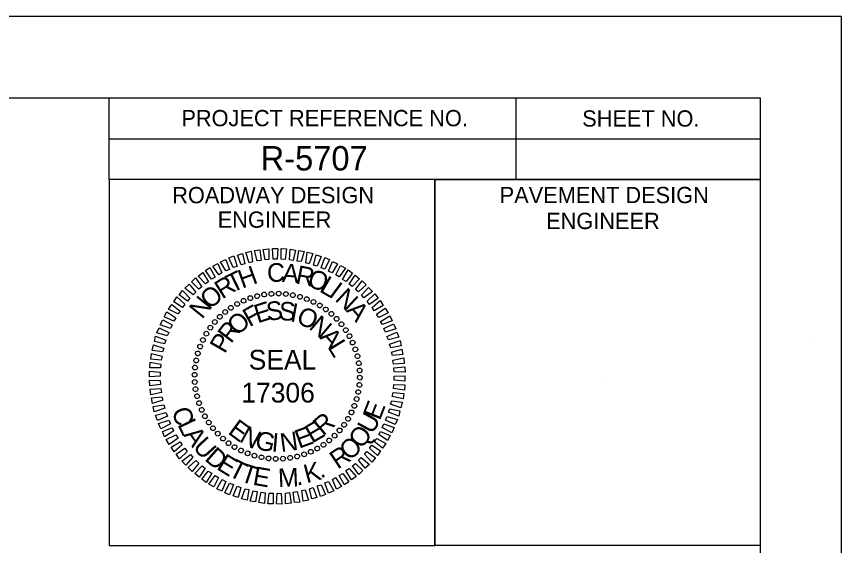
# Model space of a CAD drawing. Extents: x 573078 to 573116.6, y -55221.3 to -55199.3.
# Drawn here: x 573106.94 to 573112.01, y -55202.55 to -55199.3 of the extents above; entities that cross this region are included whole.
import ezdxf

# ---------------------------------------------------------------- set-up
doc = ezdxf.new("R2010")
doc.units = 0
for name, color, linetype in [('Prop Dimension', 7, 'Continuous'), ('Scratch_Level_1', 7, 'Continuous'), ('Sheet Clip Boundary CELL', 7, 'Continuous'), ('Sheet Data Field CELL', 7, 'Continuous'), ('Sheet Plan CELL', 7, 'Continuous'), ('Sheet Plot Border Inside CELL', 7, 'Continuous')]:
    doc.layers.add(name, color=color, linetype=linetype)

msp = doc.modelspace()

# ---------------------------------------------------------------- linework, layer by layer
at = {"layer": 'Prop Dimension'}
for p, q in [((573108.38, -55201.0284), (573108.38, -55201.0284)), ((573108.4225, -55201.0163), (573108.4225, -55201.0163)), ((573108.467, -55201.0082), (573108.467, -55201.0082)), ((573108.5105, -55201.0021), (573108.5105, -55201.0021)), ((573108.555, -55201.0012), (573108.555, -55201.0012)), ((573108.5996, -55201.0041), (573108.5996, -55201.0041)), ((573108.6432, -55201.0113), (573108.6432, -55201.0113)), ((573108.6857, -55201.0203), (573108.6857, -55201.0203)), ((573108.2999, -55201.0649), (573108.2999, -55201.0649)), ((573108.3395, -55201.0446), (573108.3395, -55201.0446)), ((573108.7283, -55201.0345), (573108.7283, -55201.0345)), ((573108.7688, -55201.0527), (573108.7688, -55201.0527)), ((573108.8081, -55201.073), (573108.8081, -55201.073)), ((573108.2261, -55201.1135), (573108.2261, -55201.1135)), ((573108.2614, -55201.0883), (573108.2614, -55201.0883)), ((573108.8446, -55201.0984), (573108.8446, -55201.0984)), ((573108.8801, -55201.1256), (573108.8801, -55201.1256)), ((573108.1622, -55201.1753), (573108.1622, -55201.1753)), ((573108.1925, -55201.1438), (573108.1925, -55201.1438)), ((573108.9114, -55201.156), (573108.9114, -55201.156)), ((573108.1349, -55201.2107), (573108.1349, -55201.2107)), ((573108.9418, -55201.1895), (573108.9418, -55201.1895)), ((573108.9672, -55201.2248), (573108.9672, -55201.2248)), ((573108.0893, -55201.2867), (573108.0893, -55201.2867)), ((573108.1095, -55201.2471), (573108.1095, -55201.2471)), ((573108.9904, -55201.2633), (573108.9904, -55201.2633)), ((573108.071, -55201.3272), (573108.071, -55201.3272)), ((573109.0106, -55201.3029), (573109.0106, -55201.3029)), ((573108.0569, -55201.3697), (573108.0569, -55201.3697)), ((573109.0268, -55201.3434), (573109.0268, -55201.3434)), ((573109.039, -55201.3859), (573109.039, -55201.3859)), ((573108.0479, -55201.4123), (573108.0479, -55201.4123)), ((573109.0471, -55201.4305), (573109.0471, -55201.4305)), ((573108.0407, -55201.4557), (573108.0407, -55201.4557)), ((573109.0532, -55201.4739), (573109.0532, -55201.4739)), ((573108.0377, -55201.5002), (573108.0377, -55201.5002)), ((573108.546, -55201.5095), (573108.546, -55201.5095)), ((573109.0543, -55201.5185), (573109.0543, -55201.5185)), ((573108.0386, -55201.5448), (573108.0386, -55201.5448)), ((573108.0447, -55201.5884), (573108.0447, -55201.5884)), ((573109.0511, -55201.563), (573109.0511, -55201.563)), ((573108.0528, -55201.633), (573108.0528, -55201.633)), ((573109.0442, -55201.6067), (573109.0442, -55201.6067)), ((573108.065, -55201.6755), (573108.065, -55201.6755)), ((573109.0208, -55201.6917), (573109.0208, -55201.6917)), ((573109.0349, -55201.6492), (573109.0349, -55201.6492)), ((573108.0812, -55201.716), (573108.0812, -55201.716)), ((573109.0025, -55201.7322), (573109.0025, -55201.7322)), ((573108.1014, -55201.7554), (573108.1014, -55201.7554)), ((573108.1248, -55201.7939), (573108.1248, -55201.7939)), ((573108.9823, -55201.7716), (573108.9823, -55201.7716)), ((573108.15, -55201.8294), (573108.15, -55201.8294)), ((573108.9296, -55201.8436), (573108.9296, -55201.8436)), ((573108.9571, -55201.808), (573108.9571, -55201.808)), ((573108.1804, -55201.8627), (573108.1804, -55201.8627)), ((573108.2119, -55201.8931), (573108.2119, -55201.8931)), ((573108.8993, -55201.8749), (573108.8993, -55201.8749)), ((573108.2472, -55201.9205), (573108.2472, -55201.9205)), ((573108.2837, -55201.9457), (573108.2837, -55201.9457)), ((573108.8304, -55201.9307), (573108.8304, -55201.9307)), ((573108.866, -55201.9052), (573108.866, -55201.9052)), ((573108.3233, -55201.966), (573108.3233, -55201.966)), ((573108.3638, -55201.9842), (573108.3638, -55201.9842)), ((573108.7121, -55201.9903), (573108.7121, -55201.9903)), ((573108.7526, -55201.9741), (573108.7526, -55201.9741)), ((573108.7919, -55201.9538), (573108.7919, -55201.9538)), ((573108.4063, -55201.9984), (573108.4063, -55201.9984)), ((573108.4488, -55202.0076), (573108.4488, -55202.0076)), ((573108.4922, -55202.0146), (573108.4922, -55202.0146)), ((573108.5368, -55202.0177), (573108.5368, -55202.0177)), ((573108.5813, -55202.0166), (573108.5813, -55202.0166)), ((573108.625, -55202.0105), (573108.625, -55202.0105)), ((573108.6695, -55202.0024), (573108.6695, -55202.0024))]:
    msp.add_line(p, q, dxfattribs=at)
for points in [[(573108.4711, -55200.7946), (573108.4598, -55200.7298), (573108.4943, -55200.7258), (573108.4954, -55200.7915)], [(573108.5217, -55200.7895), (573108.5165, -55200.7238), (573108.5501, -55200.7247), (573108.546, -55200.7906)], [(573108.5703, -55200.7906), (573108.5703, -55200.7247), (573108.6036, -55200.7258), (573108.5946, -55200.7915)], [(573108.6209, -55200.7935), (573108.625, -55200.7278), (573108.6583, -55200.7339), (573108.6452, -55200.7976)], [(573108.2756, -55200.8412), (573108.2492, -55200.7825), (573108.2796, -55200.7703), (573108.301, -55200.8351)], [(573108.3253, -55200.825), (573108.3019, -55200.7643), (573108.3334, -55200.755), (573108.3464, -55200.8178)], [(573108.3739, -55200.8117), (573108.3525, -55200.7481), (573108.3869, -55200.7409), (573108.395, -55200.8068)], [(573108.4225, -55200.8007), (573108.4063, -55200.7359), (573108.4396, -55200.7328), (573108.4468, -55200.7976)], [(573108.6695, -55200.8016), (573108.6785, -55200.7368), (573108.7121, -55200.742), (573108.6938, -55200.8048)], [(573108.7211, -55200.8129), (573108.7312, -55200.7469), (573108.7656, -55200.755), (573108.7424, -55200.8178)], [(573108.7697, -55200.8259), (573108.785, -55200.7631), (573108.8162, -55200.7733), (573108.791, -55200.8331)], [(573108.1876, -55200.8867), (573108.15, -55200.832), (573108.1815, -55200.8158), (573108.2067, -55200.8745)], [(573108.231, -55200.8624), (573108.1986, -55200.8057), (573108.2301, -55200.7915), (573108.2533, -55200.8534)], [(573108.8153, -55200.8441), (573108.8385, -55200.7805), (573108.8669, -55200.7926), (573108.8385, -55200.8513)], [(573108.8608, -55200.8635), (573108.8862, -55200.8036), (573108.9175, -55200.8178), (573108.8831, -55200.8745)], [(573108.9074, -55200.8867), (573108.9348, -55200.8291), (573108.9652, -55200.8462), (573108.9267, -55200.8988)], [(573108.1046, -55200.9425), (573108.0609, -55200.8939), (573108.0884, -55200.8725), (573108.1237, -55200.9292)], [(573108.143, -55200.9121), (573108.1055, -55200.8603), (573108.1318, -55200.8412), (573108.1653, -55200.8999)], [(573108.947, -55200.9141), (573108.9823, -55200.8554), (573109.0086, -55200.8765), (573108.9692, -55200.9263)], [(573108.0641, -55200.9737), (573108.0195, -55200.9292), (573108.0438, -55200.9049), (573108.0832, -55200.9596)], [(573108.9884, -55200.9445), (573109.0259, -55200.8887), (573109.0523, -55200.911), (573109.0077, -55200.9587)], [(573109.0268, -55200.9758), (573109.0685, -55200.9231), (573109.0928, -55200.9474), (573109.0462, -55200.9911)], [(573107.9952, -55201.0478), (573107.9426, -55201.0082), (573107.9648, -55200.9818), (573108.0094, -55201.0295)], [(573108.0305, -55201.0093), (573107.979, -55200.9677), (573108.0042, -55200.9445), (573108.0467, -55200.9931)], [(573109.0633, -55201.0113), (573109.1069, -55200.9636), (573109.1312, -55200.9879), (573109.0786, -55201.0275)], [(573107.9648, -55201.0862), (573107.9102, -55201.0518), (573107.9293, -55201.0223), (573107.9779, -55201.0669)], [(573109.0988, -55201.0478), (573109.1454, -55201.0021), (573109.1666, -55201.0295), (573109.113, -55201.068)], [(573107.9345, -55201.1267), (573107.8778, -55201.0964), (573107.898, -55201.068), (573107.9507, -55201.1085)], [(573109.1292, -55201.0871), (573109.1787, -55201.0446), (573109.1981, -55201.0741), (573109.1414, -55201.1065)], [(573107.9102, -55201.1702), (573107.8523, -55201.145), (573107.8676, -55201.1135), (573107.9223, -55201.151)], [(573109.1555, -55201.1288), (573109.2091, -55201.0903), (573109.2284, -55201.1207), (573109.1697, -55201.149)], [(573107.8899, -55201.2167), (573107.8271, -55201.1936), (573107.8422, -55201.1621), (573107.9, -55201.1945)], [(573109.1819, -55201.1733), (573109.2386, -55201.1378), (573109.2516, -55201.1693), (573109.194, -55201.1924)], [(573107.8697, -55201.2613), (573107.8069, -55201.2431), (573107.8199, -55201.2118), (573107.8807, -55201.2401)], [(573109.2021, -55201.2167), (573109.2617, -55201.1864), (573109.275, -55201.2188), (573109.2122, -55201.239)], [(573107.8544, -55201.3099), (573107.7916, -55201.2968), (573107.7988, -55201.2633), (573107.8625, -55201.2887)], [(573109.2203, -55201.2644), (573109.282, -55201.2381), (573109.2932, -55201.2694), (573109.2305, -55201.2856)], [(573107.8413, -55201.3585), (573107.7785, -55201.3504), (573107.7855, -55201.316), (573107.8494, -55201.3373)], [(573109.2365, -55201.313), (573109.3013, -55201.2896), (573109.3074, -55201.3232), (573109.2435, -55201.3342)], [(573107.8332, -55201.4102), (573107.7684, -55201.4042), (573107.7725, -55201.3697), (573107.8382, -55201.3859)], [(573109.2487, -55201.3616), (573109.3124, -55201.3423), (573109.3184, -55201.3767), (573109.2548, -55201.3828)], [(573107.828, -55201.4588), (573107.7623, -55201.4568), (573107.7644, -55201.4233), (573107.8301, -55201.4345)], [(573109.2577, -55201.4102), (573109.3236, -55201.3961), (573109.3265, -55201.4305), (573109.2617, -55201.4345)], [(573107.8271, -55201.5095), (573107.7612, -55201.5124), (573107.7612, -55201.478), (573107.8271, -55201.4852)], [(573109.2638, -55201.4588), (573109.3297, -55201.4507), (573109.3317, -55201.4852), (573109.2658, -55201.4831)], [(573107.828, -55201.5601), (573107.7623, -55201.5682), (573107.7603, -55201.5338), (573107.826, -55201.5358)], [(573109.2649, -55201.5095), (573109.3306, -55201.5063), (573109.3306, -55201.5407), (573109.2649, -55201.5338)], [(573107.8341, -55201.6087), (573107.7684, -55201.6229), (573107.7653, -55201.5884), (573107.8301, -55201.5844)], [(573109.2638, -55201.5601), (573109.3297, -55201.5621), (573109.3277, -55201.5954), (573109.2617, -55201.5844)], [(573107.8433, -55201.6573), (573107.7794, -55201.6764), (573107.7734, -55201.642), (573107.8373, -55201.6359)], [(573109.2588, -55201.6087), (573109.3236, -55201.6148), (573109.3196, -55201.6492), (573109.2536, -55201.633)], [(573107.8555, -55201.7059), (573107.7907, -55201.7291), (573107.7846, -55201.6958), (573107.8483, -55201.6845)], [(573109.2507, -55201.6602), (573109.3135, -55201.6683), (573109.3063, -55201.7027), (573109.2426, -55201.6816)], [(573107.8717, -55201.7545), (573107.8098, -55201.7808), (573107.7988, -55201.7493), (573107.8616, -55201.7331)], [(573109.2374, -55201.7088), (573109.3002, -55201.7221), (573109.2932, -55201.7554), (573109.2293, -55201.7302)], [(573107.8899, -55201.802), (573107.8301, -55201.8323), (573107.817, -55201.7999), (573107.8798, -55201.7797)], [(573109.2224, -55201.7574), (573109.2851, -55201.7756), (573109.2719, -55201.8071), (573109.2111, -55201.7788)], [(573107.9102, -55201.8456), (573107.8535, -55201.8809), (573107.8402, -55201.8497), (573107.898, -55201.8263)], [(573109.2021, -55201.802), (573109.2649, -55201.8254), (573109.2496, -55201.8566), (573109.192, -55201.8242)], [(573107.9365, -55201.8902), (573107.8827, -55201.9286), (573107.8636, -55201.8983), (573107.9223, -55201.8699)], [(573109.1576, -55201.8922), (573109.2143, -55201.9226), (573109.194, -55201.9509), (573109.1414, -55201.9104)], [(573109.1819, -55201.8485), (573109.2395, -55201.874), (573109.2244, -55201.9052), (573109.1697, -55201.8679)], [(573107.9628, -55201.9316), (573107.9131, -55201.9741), (573107.894, -55201.9448), (573107.9507, -55201.9124)], [(573109.1272, -55201.9327), (573109.1819, -55201.9671), (573109.1625, -55201.9964), (573109.1139, -55201.9518)], [(573107.9932, -55201.9712), (573107.9466, -55202.0166), (573107.9252, -55201.9894), (573107.979, -55201.9509)], [(573108.0285, -55202.0076), (573107.9851, -55202.0551), (573107.9608, -55202.0308), (573108.0134, -55201.9914)], [(573109.0968, -55201.9712), (573109.1495, -55202.0105), (573109.1272, -55202.0369), (573109.0826, -55201.9894)], [(573108.065, -55202.0429), (573108.0236, -55202.0956), (573107.9993, -55202.0713), (573108.0458, -55202.0279)], [(573109.028, -55202.045), (573109.0725, -55202.0895), (573109.0482, -55202.1138), (573109.0086, -55202.0591)], [(573109.0613, -55202.0096), (573109.113, -55202.051), (573109.0876, -55202.0744), (573109.0451, -55202.0258)], [(573108.1034, -55202.0744), (573108.0661, -55202.13), (573108.0398, -55202.1077), (573108.0843, -55202.0603)], [(573108.1451, -55202.1048), (573108.1095, -55202.1635), (573108.0832, -55202.1422), (573108.1228, -55202.0927)], [(573108.9875, -55202.0765), (573109.0309, -55202.1251), (573109.0037, -55202.1462), (573108.9681, -55202.0895)], [(573108.1844, -55202.132), (573108.1572, -55202.1899), (573108.1268, -55202.1725), (573108.1653, -55202.1199)], [(573108.231, -55202.1554), (573108.2058, -55202.2151), (573108.1743, -55202.2009), (573108.2087, -55202.1442)], [(573108.9044, -55202.132), (573108.9418, -55202.1867), (573108.9105, -55202.2029), (573108.8851, -55202.1442)], [(573108.949, -55202.1068), (573108.9863, -55202.1584), (573108.96, -55202.1777), (573108.9267, -55202.119)], [(573108.2767, -55202.1746), (573108.2533, -55202.2385), (573108.2249, -55202.2263), (573108.2533, -55202.1676)], [(573108.3221, -55202.1928), (573108.3071, -55202.2556), (573108.2756, -55202.2454), (573108.301, -55202.1858)], [(573108.7667, -55202.1939), (573108.7899, -55202.2547), (573108.7586, -55202.2637), (573108.7454, -55202.2009)], [(573108.8162, -55202.1777), (573108.8426, -55202.2364), (573108.8122, -55202.2486), (573108.791, -55202.1838)], [(573108.8608, -55202.1563), (573108.8932, -55202.213), (573108.8619, -55202.2272), (573108.8385, -55202.1656)], [(573108.3707, -55202.2061), (573108.3606, -55202.2718), (573108.3262, -55202.2637), (573108.3496, -55202.2009)], [(573108.4225, -55202.2171), (573108.4133, -55202.2819), (573108.38, -55202.2769), (573108.3982, -55202.2142)], [(573108.4711, -55202.2252), (573108.467, -55202.2911), (573108.4335, -55202.285), (573108.4468, -55202.2211)], [(573108.5217, -55202.2283), (573108.5217, -55202.294), (573108.4882, -55202.2931), (573108.4974, -55202.2272)], [(573108.5703, -55202.2292), (573108.5753, -55202.2952), (573108.542, -55202.294), (573108.546, -55202.2283)], [(573108.6209, -55202.2243), (573108.632, -55202.2891), (573108.5975, -55202.2931), (573108.5966, -55202.2272)], [(573108.6695, -55202.2182), (573108.6857, -55202.283), (573108.6522, -55202.2859), (573108.6452, -55202.2211)], [(573108.7181, -55202.207), (573108.7393, -55202.2709), (573108.7049, -55202.2778), (573108.6968, -55202.2121)]]:
    msp.add_lwpolyline(points, close=True, dxfattribs=at)
for centre, major_axis in [((573108.3394, -55201.0454), (-0.0059, 0.0133)), ((573108.3807, -55201.0292), (-0.0047, 0.0138)), ((573108.4232, -55201.0166), (-0.0035, 0.0141)), ((573108.4666, -55201.0078), (-0.0023, 0.0144)), ((573108.5106, -55201.0028), (-0.001, 0.0145)), ((573108.5549, -55201.0016), (0.0003, 0.0146)), ((573108.5991, -55201.0043), (0.0015, 0.0145)), ((573108.6429, -55201.0109), (0.0028, 0.0143)), ((573108.686, -55201.0212), (0.004, 0.014)), ((573108.728, -55201.0353), (0.0052, 0.0136)), ((573108.262, -55201.0884), (-0.0082, 0.0121)), ((573108.2998, -55201.0652), (-0.0071, 0.0128)), ((573108.7687, -55201.0529), (0.0064, 0.0131)), ((573108.8076, -55201.0741), (0.0075, 0.0125)), ((573108.8445, -55201.0985), (0.0086, 0.0118)), ((573108.1932, -55201.1441), (-0.0101, 0.0105)), ((573108.2264, -55201.1147), (-0.0092, 0.0113)), ((573108.8792, -55201.1261), (0.0096, 0.011)), ((573108.1627, -55201.1762), (-0.011, 0.0096)), ((573108.9113, -55201.1566), (0.0105, 0.0101)), ((573108.9407, -55201.1898), (0.0113, 0.0092)), ((573108.1107, -55201.2478), (-0.0125, 0.0075)), ((573108.1351, -55201.2109), (-0.0118, 0.0086)), ((573108.9671, -55201.2254), (0.0121, 0.0082)), ((573108.0895, -55201.2868), (-0.0131, 0.0064)), ((573108.9902, -55201.2632), (0.0128, 0.0071)), ((573109.01, -55201.3028), (0.0133, 0.0059)), ((573108.0719, -55201.3274), (-0.0136, 0.0052)), ((573109.0262, -55201.3441), (0.0138, 0.0047)), ((573108.0578, -55201.3694), (-0.014, 0.004)), ((573109.0388, -55201.3865), (0.0141, 0.0035)), ((573108.0475, -55201.4125), (-0.0143, 0.0028)), ((573109.0476, -55201.4299), (0.0144, 0.0023)), ((573108.0382, -55201.5005), (-0.0146, 0.0003)), ((573108.0409, -55201.4563), (-0.0145, 0.0015)), ((573109.0527, -55201.474), (0.0145, 0.001)), ((573108.0394, -55201.5448), (-0.0145, -0.001)), ((573109.0538, -55201.5183), (0.0146, -0.0003)), ((573108.0444, -55201.5888), (-0.0144, -0.0023)), ((573109.0446, -55201.6063), (0.0143, -0.0028)), ((573109.0511, -55201.5625), (0.0145, -0.0015)), ((573108.0532, -55201.6323), (-0.0141, -0.0035)), ((573109.0342, -55201.6494), (0.014, -0.004)), ((573108.0658, -55201.6747), (-0.0138, -0.0047)), ((573109.0202, -55201.6914), (0.0136, -0.0052)), ((573108.0821, -55201.716), (-0.0133, -0.0059)), ((573108.1018, -55201.7556), (-0.0128, -0.0071)), ((573109.0025, -55201.732), (0.0131, -0.0064)), ((573108.125, -55201.7934), (-0.0121, -0.0082)), ((573108.9569, -55201.8079), (0.0118, -0.0086)), ((573108.9813, -55201.771), (0.0125, -0.0075)), ((573108.1513, -55201.829), (-0.0113, -0.0092)), ((573108.9293, -55201.8426), (0.011, -0.0096)), ((573108.1807, -55201.8622), (-0.0105, -0.0101)), ((573108.2128, -55201.8927), (-0.0096, -0.011)), ((573108.8656, -55201.9041), (0.0092, -0.0113)), ((573108.8988, -55201.8747), (0.0101, -0.0105)), ((573108.2475, -55201.9203), (-0.0086, -0.0118)), ((573108.2844, -55201.9447), (-0.0075, -0.0125)), ((573108.7922, -55201.9536), (0.0071, -0.0128)), ((573108.83, -55201.9304), (0.0082, -0.0121)), ((573108.3234, -55201.9659), (-0.0064, -0.0131)), ((573108.364, -55201.9835), (-0.0052, -0.0136)), ((573108.406, -55201.9976), (-0.004, -0.014)), ((573108.4491, -55202.0079), (-0.0028, -0.0143)), ((573108.6255, -55202.011), (0.0023, -0.0144)), ((573108.6689, -55202.0022), (0.0035, -0.0141)), ((573108.7114, -55201.9896), (0.0047, -0.0138)), ((573108.7526, -55201.9734), (0.0059, -0.0133)), ((573108.4929, -55202.0145), (-0.0015, -0.0145)), ((573108.5372, -55202.0172), (-0.0003, -0.0146)), ((573108.5814, -55202.016), (0.001, -0.0145))]:
    msp.add_ellipse(centre, major_axis=major_axis, ratio=0.999708, dxfattribs=at)
at = {"layer": 'Scratch_Level_1'}
for p, q in [((573108.546, -55201.5095), (573108.546, -55201.5095)), ((573110.547, -55201.5095), (573110.547, -55201.5095))]:
    msp.add_line(p, q, dxfattribs=at)
at = {"layer": 'Sheet Clip Boundary CELL'}
msp.add_line((573111.8452, -55201.263), (573111.8452, -55201.263), dxfattribs=at)
at = {"layer": 'Sheet Plan CELL'}
for p, q in [((573110.0144, -55200.2999), (573110.0144, -55199.7984)), ((573107.5132, -55200.0494), (573111.5142, -55200.0497)), ((573109.5142, -55200.3002), (573109.5144, -55202.5494))]:
    msp.add_line(p, q, dxfattribs=at)
for points in [[(573081.5142, -55199.7984), (573111.5142, -55199.7984), (573111.5142, -55220.7984), (573081.5142, -55220.7984)], [(573107.5132, -55199.7984), (573111.5142, -55199.7984), (573111.5142, -55200.3002), (573107.5132, -55200.3002)], [(573109.5142, -55200.3002), (573107.5132, -55200.3002), (573107.5132, -55202.5502), (573109.5142, -55202.5502)], [(573109.5142, -55200.3002), (573111.5142, -55200.3002), (573111.5142, -55202.5502), (573109.5142, -55202.5502)]]:
    msp.add_lwpolyline(points, close=True, dxfattribs=at)
at = {"layer": 'Sheet Plot Border Inside CELL'}
msp.add_lwpolyline([(573112.0142, -55199.2984), (573078.0142, -55199.2984), (573078.0142, -55221.2984), (573112.0142, -55221.2984)], close=True, dxfattribs=at)

# ---------------------------------------------------------------- texts
at = {"layer": 'Prop Dimension'}
for s, height, rotation, p in [('H', 0.1144, 19.8207, (573108.3305, -55200.9715)), ('C', 0.1144, 1.0718, (573108.4844, -55200.9301)), ('A', 0.1144, 354.8222, (573108.5735, -55200.929)), ('R', 0.1144, 348.5725, (573108.6545, -55200.9382)), ('T', 0.1144, 26.0703, (573108.2688, -55200.9998)), ('O', 0.1144, 342.3229, (573108.7253, -55200.9564)), ('R', 0.1144, 32.3199, (573108.2081, -55201.0383)), ('L', 0.1144, 329.8237, (573108.7994, -55200.9857)), ('I', 0.1144, 323.5741, (573108.8561, -55201.0151)), ('O', 0.1144, 38.5695, (573108.13, -55201.1022)), ('N', 0.1144, 317.3244, (573108.8954, -55201.0415)), ('N', 0.1144, 51.0688, (573108.0845, -55201.163)), ('F', 0.1144, 29.3, (573108.3761, -55201.2095)), ('E', 0.1144, 17.6709, (573108.4256, -55201.1852)), ('S', 0.1144, 6.1833, (573108.4844, -55201.169)), ('S', 0.1144, 358.4778, (573108.5564, -55201.1659)), ('I', 0.1144, 350.0931, (573108.6212, -55201.1711)), ('A', 0.1144, 311.0748, (573108.9654, -55201.1072)), ('O', 0.1144, 43.5875, (573108.3041, -55201.2642)), ('O', 0.1144, 335.3611, (573108.6565, -55201.178)), ('N', 0.1144, 319.95, (573108.7355, -55201.2136)), ('R', 0.1144, 52.4166, (573108.2616, -55201.3128)), ('A', 0.1144, 312.2445, (573108.8023, -55201.2732)), ('P', 0.1144, 60.1222, (573108.2243, -55201.3756)), ('L', 0.1144, 301.6752, (573108.8529, -55201.3299)), ('SEAL', 0.1215, 0, (573108.371, -55201.4687)), ('17306', 0.1215, 0, (573108.3255, -55201.6712)), ('E', 0.1144, 68.6635, (573109.1769, -55201.7855)), ('C', 0.1144, 287.4003, (573107.8971, -55201.7187)), ('R', 0.1144, 40.7353, (573108.8277, -55201.8798)), ('U', 0.1144, 61.3078, (573109.1324, -55201.8706)), ('L', 0.1144, 295.5141, (573107.9315, -55201.8058)), ('E', 0.1144, 323.6798, (573108.2373, -55201.8584)), ('E', 0.1144, 30.1214, (573108.7598, -55201.9244)), ('A', 0.1144, 306.1492, (573107.9671, -55201.8706)), ('N', 0.1144, 331.3854, (573108.3073, -55201.9082)), ('E', 0.1144, 20.0411, (573108.6799, -55201.9556)), ('Q', 0.1144, 52.3928, (573109.0646, -55201.9608)), ('U', 0.1144, 312.3988, (573108.0227, -55201.9475)), ('G', 0.1144, 346.7965, (573108.4034, -55201.9527)), ('I', 0.1144, 355.0405, (573108.5087, -55201.9718)), ('N', 0.1144, 7.7341, (573108.5705, -55201.9759)), ('O', 0.1144, 39.8936, (573108.9877, -55202.0326)), ('D', 0.1144, 318.6484, (573108.0947, -55202.0216)), ('R', 0.1144, 33.6439, (573108.9177, -55202.0843)), ('E', 0.1144, 328.3523, (573108.1676, -55202.0771)), ('T', 0.1144, 333.6523, (573108.2393, -55202.1176)), ('T', 0.1144, 341.812, (573108.3122, -55202.1521)), ('K', 0.1144, 14.8951, (573108.7265, -55202.1683)), ('E', 0.1144, 349.8966, (573108.3912, -55202.1755)), ('M', 0.1144, 2.3958, (573108.5532, -55202.1917)), ('.', 0.1144, 21.1447, (573108.8124, -55202.139)), ('.', 0.1144, 8.6454, (573108.6666, -55202.1815))]:
    msp.add_text(s, height=height, rotation=rotation, dxfattribs=at).set_placement(p)
at = {"layer": 'Sheet Data Field CELL'}
msp.add_text('R-5707', height=0.15, rotation=0, dxfattribs=at).set_placement((573108.4444, -55200.2449))
at = {"layer": 'Sheet Plan CELL'}
for s, height, p in [('PROJECT REFERENCE NO.', 0.100002, (573107.9572, -55199.9729)), ('SHEET NO.', 0.1, (573110.4204, -55199.9752)), ('ROADWAY DESIGN', 0.100002, (573107.9007, -55200.4462)), ('PAVEMENT DESIGN', 0.100002, (573109.9133, -55200.4457)), ('ENGINEER', 0.1, (573108.1804, -55200.5969)), ('ENGINEER', 0.1, (573110.1987, -55200.6049))]:
    msp.add_text(s, height=height, rotation=0, dxfattribs=at).set_placement(p)

doc.saveas('drawing.dxf')
